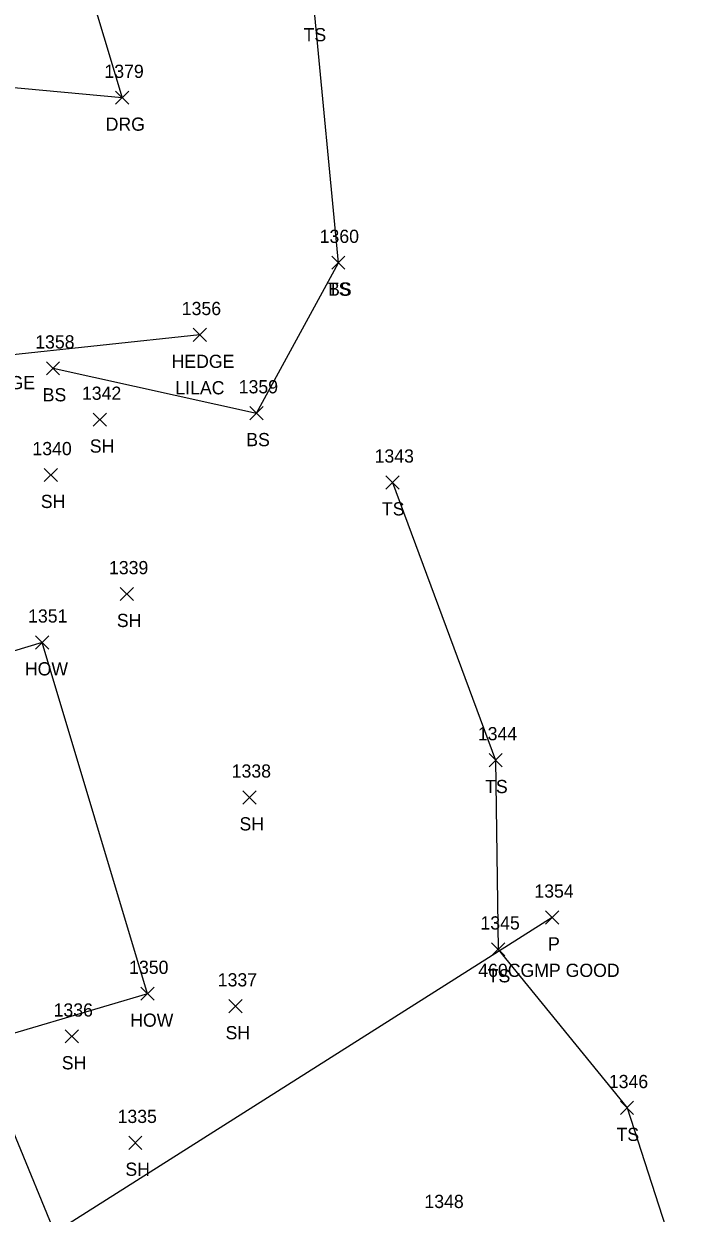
# Model space of a CAD drawing. Extents: x 462930 to 463548, y 29607 to 30453.
# Drawn here: x 463364 to 463394.4, y 30004.8 to 30059.7 of the extents above; entities that cross this region are included whole.
import ezdxf

# ---------------------------------------------------------------- set-up
doc = ezdxf.new("R2010")
doc.units = 0
for name, color, linetype in [('D_A', 7, 'Continuous'), ('D_C', 7, 'Continuous'), ('D_I', 7, 'Continuous'), ('D_TIC', 7, 'Continuous'), ('DCP', 7, 'Continuous'), ('L_A', 7, 'Continuous'), ('L_C', 7, 'Continuous'), ('L_I', 7, 'Continuous'), ('L_TIC', 7, 'Continuous'), ('LAHR', 7, 'Continuous'), ('LBC', 7, 'Continuous'), ('LELB', 7, 'Continuous'), ('R_A', 7, 'Continuous'), ('R_I', 7, 'Continuous'), ('R_TIC', 7, 'Continuous'), ('RDG', 7, 'Continuous')]:
    doc.layers.add(name, color=color, linetype=linetype)

msp = doc.modelspace()

# ---------------------------------------------------------------- linework, layer by layer
at = {"layer": 'D_TIC'}
for points in [[(463388.073, 30018.132), (463388.683, 30018.742)], [(463388.683, 30018.132), (463388.073, 30018.742)]]:
    msp.add_lwpolyline(points, dxfattribs=at)
at = {"layer": 'DCP'}
msp.add_lwpolyline([(463388.378, 30018.437), (463356.051, 29997.965)], dxfattribs=at)
at = {"layer": 'L_TIC'}
for points in [[(463378.211, 30048.343), (463378.821, 30048.953)], [(463378.821, 30048.343), (463378.211, 30048.953)], [(463378.211, 30048.343), (463378.821, 30048.953)], [(463378.821, 30048.343), (463378.211, 30048.953)], [(463371.825, 30045.012), (463372.435, 30045.622)], [(463372.435, 30045.012), (463371.825, 30045.622)], [(463365.047, 30043.47), (463365.657, 30044.08)], [(463365.657, 30043.47), (463365.047, 30044.08)], [(463367.204, 30041.103), (463367.814, 30041.713)], [(463367.814, 30041.103), (463367.204, 30041.713)], [(463374.438, 30041.401), (463375.048, 30042.011)], [(463375.048, 30041.401), (463374.438, 30042.011)], [(463364.945, 30038.548), (463365.555, 30039.158)], [(463365.555, 30038.548), (463364.945, 30039.158)], [(463380.704, 30038.206), (463381.314, 30038.816)], [(463381.314, 30038.206), (463380.704, 30038.816)], [(463368.453, 30033.056), (463369.063, 30033.666)], [(463369.063, 30033.056), (463368.453, 30033.666)], [(463364.546, 30030.824), (463365.156, 30031.434)], [(463365.156, 30030.824), (463364.546, 30031.434)], [(463385.465, 30025.393), (463386.075, 30026.003)], [(463386.075, 30025.393), (463385.465, 30026.003)], [(463374.111, 30023.671), (463374.721, 30024.281)], [(463374.721, 30023.671), (463374.111, 30024.281)], [(463385.587, 30016.662), (463386.197, 30017.272)], [(463386.197, 30016.662), (463385.587, 30017.272)], [(463369.405, 30014.615), (463370.015, 30015.225)], [(463370.015, 30014.615), (463369.405, 30015.225)], [(463373.468, 30014.037), (463374.078, 30014.647)], [(463374.078, 30014.037), (463373.468, 30014.647)], [(463365.913, 30012.646), (463366.523, 30013.256)], [(463366.523, 30012.646), (463365.913, 30013.256)], [(463391.526, 30009.344), (463392.136, 30009.954)], [(463392.136, 30009.344), (463391.526, 30009.954)], [(463368.847, 30007.735), (463369.457, 30008.345)], [(463369.457, 30007.735), (463368.847, 30008.345)]]:
    msp.add_lwpolyline(points, dxfattribs=at)
at = {"layer": 'LAHR'}
msp.add_lwpolyline([(463372.13, 30045.317), (463362.936, 30044.335)], dxfattribs=at)
at = {"layer": 'LBC'}
for points in [[(463364.851, 30031.129), (463354.213, 30027.904)], [(463369.71, 30014.92), (463364.851, 30031.129)], [(463369.71, 30014.92), (463359.086, 30011.774)]]:
    msp.add_lwpolyline(points, dxfattribs=at)
at = {"layer": 'LELB'}
for points in [[(463378.516, 30048.648), (463377.397, 30060.388), (463373.955, 30062.949), (463378.381, 30068.216), (463380.763, 30073.646), (463377.061, 30079.056), (463368.749, 30077.741), (463357.917, 30075.38), (463358.238, 30073.999), (463362.431, 30074.488), (463362.024, 30068.592), (463364.125, 30068.673), (463364.188, 30075.412), (463369.759, 30071.787), (463365.468, 30065.245), (463360.854, 30066.478), (463353.772, 30065.008)], [(463365.352, 30043.775), (463374.743, 30041.706), (463378.516, 30048.648)], [(463381.009, 30038.511), (463385.77, 30025.698), (463385.892, 30016.967), (463391.831, 30009.649), (463394.423, 30001.658), (463383.306, 30004.117)]]:
    msp.add_lwpolyline(points, dxfattribs=at)
at = {"layer": 'R_TIC'}
for points in [[(463368.242, 30055.956), (463368.852, 30056.566)], [(463368.852, 30055.956), (463368.242, 30056.566)]]:
    msp.add_lwpolyline(points, dxfattribs=at)
at = {"layer": 'RDG'}
for points in [[(463355.188, 30061.475), (463366.856, 30061.901), (463368.547, 30056.261), (463358.377, 30057.19)], [(463362.287, 30011.519), (463366.742, 30000.689)]]:
    msp.add_lwpolyline(points, dxfattribs=at)

# ---------------------------------------------------------------- texts
at = {"layer": 'D_A'}
msp.add_text('P', height=0.61, dxfattribs=at).set_placement((463388.188, 30016.913))
at = {"layer": 'D_C'}
msp.add_text('460CGMP GOOD', height=0.6096, dxfattribs=at).set_placement((463384.968, 30015.694))
at = {"layer": 'D_I'}
msp.add_text('1354', height=0.6096, dxfattribs=at).set_placement((463387.557, 30019.351))
at = {"layer": 'L_A'}
for s, p in [('TS', (463376.912, 30058.864)), ('TS', (463378.031, 30047.124)), ('BS', (463378.041, 30047.124)), ('HEDGE', (463370.82, 30043.793)), ('HEDGE', (463361.626, 30042.811)), ('BS', (463364.877, 30042.251)), ('SH', (463367.048, 30039.884)), ('BS', (463374.268, 30040.182)), ('SH', (463364.789, 30037.329)), ('TS', (463380.524, 30036.987)), ('SH', (463368.297, 30031.837)), ('HOW', (463364.054, 30029.605)), ('TS', (463385.285, 30024.174)), ('SH', (463373.955, 30022.452)), ('TS', (463385.407, 30015.443)), ('HOW', (463368.913, 30013.396)), ('SH', (463373.312, 30012.818)), ('SH', (463365.757, 30011.427)), ('TS', (463391.346, 30008.125)), ('SH', (463368.691, 30006.516))]:
    msp.add_text(s, height=0.6096, dxfattribs=at).set_placement(p)
at = {"layer": 'L_C'}
msp.add_text('LILAC', height=0.6096, dxfattribs=at).set_placement((463370.995, 30042.574))
at = {"layer": 'L_I'}
for s, p in [('1360', (463377.654, 30049.562)), ('1360', (463377.654, 30049.562)), ('1356', (463371.292, 30046.231)), ('1358', (463364.531, 30044.689)), ('1359', (463373.92, 30042.62)), ('1342', (463366.688, 30042.322)), ('1340', (463364.403, 30039.767)), ('1343', (463380.188, 30039.425)), ('1339', (463367.935, 30034.275)), ('1351', (463364.203, 30032.043)), ('1344', (463384.949, 30026.612)), ('1338', (463373.595, 30024.89)), ('1345', (463385.071, 30017.881)), ('1350', (463368.863, 30015.834)), ('1337', (463372.952, 30015.256)), ('1336', (463365.38, 30013.865)), ('1346', (463390.993, 30010.563)), ('1335', (463368.331, 30008.954)), ('1348', (463382.485, 30005.031))]:
    msp.add_text(s, height=0.6096, dxfattribs=at).set_placement(p)
at = {"layer": 'R_A'}
msp.add_text('DRG', height=0.6096, dxfattribs=at).set_placement((463367.781, 30054.737))
at = {"layer": 'R_I'}
msp.add_text('1379', height=0.6096, dxfattribs=at).set_placement((463367.724, 30057.175))

doc.saveas('drawing.dxf')
